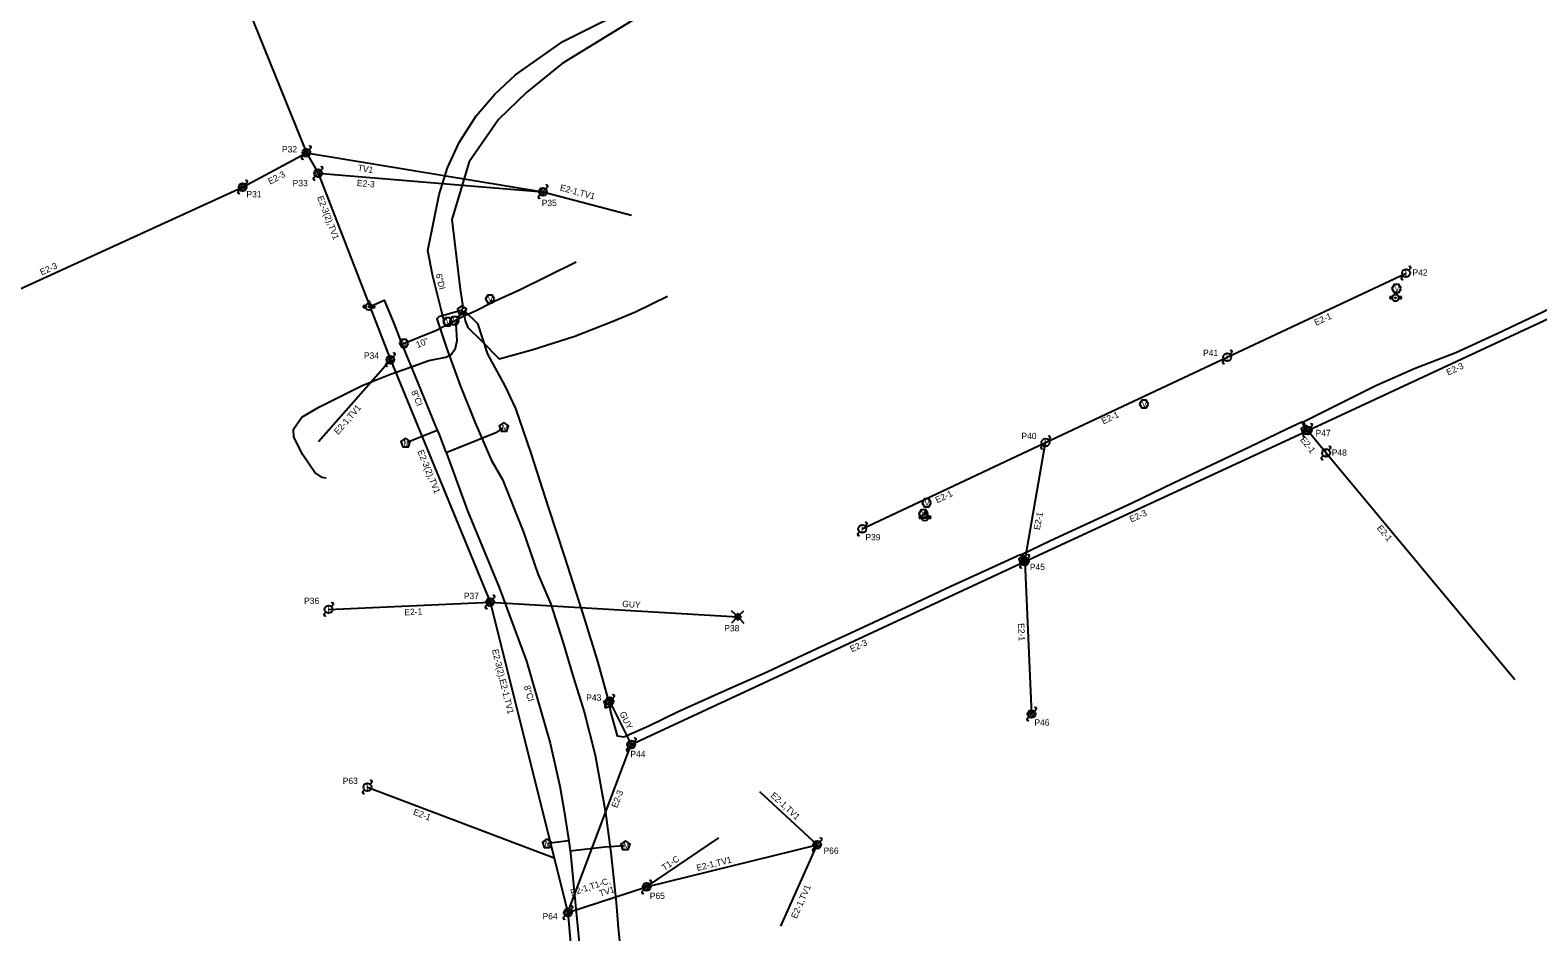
# Model space of a CAD drawing. Extents: x 1741604 to 1825760, y 1164229 to 1194908.
# Drawn here: x 1755902 to 1756853, y 1168887 to 1169455 of the extents above; entities that cross this region are included whole.
import ezdxf

# ---------------------------------------------------------------- set-up
doc = ezdxf.new("R2010")
doc.units = 0
for name, color, linetype in [('RD_EX_SU_H2O', 7, 'Continuous'), ('RD_EX_SU_Ovhd', 7, 'Continuous'), ('RD_EX_SU_Pole', 7, 'Continuous'), ('RD_EX_SU_Telecom', 7, 'Continuous'), ('RD_EX_SU_TX_H2O', 7, 'Continuous'), ('RD_EX_SU_TX_Pole', 7, 'Continuous')]:
    doc.layers.add(name, color=color, linetype=linetype)

# ---------------------------------------------------------------- blocks, each defined once
blk = doc.blocks.new('SUE_PP')
at = {"layer": 'RD_EX_SU_Pole'}
for p, q in [((-2.41, -0.65), (0.65, 2.41)), ((-1.77, -1.77), (1.77, 1.77)), ((-0.65, -2.41), (2.41, 0.65)), ((1.77, 1.77), (2.83, 2.83)), ((-2.83, -2.83), (-1.77, -1.77))]:
    blk.add_line(p, q, dxfattribs=at)
blk.add_circle((0, 0), 2.5, dxfattribs=at)
for centre, start, end in [((2.3, 3.36), 315, 135), ((-2.3, -3.36), 135, 315)]:
    blk.add_arc(centre, 0.75, start, end, dxfattribs=at)
blk = doc.blocks.new('SUE_TPP')
at = {"layer": 'RD_EX_SU_Telecom'}
blk.add_lwpolyline([(0, 3), (-2.85, 0.93), (-1.76, -2.43), (1.76, -2.43), (2.85, 0.93)], close=True, dxfattribs=at)
blk.add_text('T', height=3.75, dxfattribs=at).set_placement((-1.25, -1.88))
blk = doc.blocks.new('SUE_WV')
at = {"layer": 'RD_EX_SU_H2O'}
blk.add_lwpolyline([(2.89, 0), (1.44, 2.5), (-1.44, 2.5), (-2.89, 0), (-1.44, -2.5), (1.44, -2.5)], close=True, dxfattribs=at)
blk.add_text('V', height=3.75, dxfattribs=at).set_placement((-1.43, -1.88))
blk = doc.blocks.new('SUE_WFH')
at = {"layer": 'RD_EX_SU_H2O'}
for p, q in [((-2.01, 0.6), (-3.65, 0.6)), ((-3.65, 0.6), (-3.65, -0.45)), ((-0.48, 3.38), (-0.48, 2.04)), ((0.57, 3.38), (-0.48, 3.38)), ((0.57, 2.02), (0.57, 3.38)), ((3.7, 0.6), (2.01, 0.6)), ((3.7, -0.45), (3.7, 0.6)), ((-3.65, -0.45), (-2.05, -0.45)), ((2.05, -0.45), (3.7, -0.45))]:
    blk.add_line(p, q, dxfattribs=at)
for radius in [2.1, 0.263]:
    blk.add_circle((0, 0), radius, dxfattribs=at)
for start, end in [(163.3387, 192.31502), (74.24552, 103.21276), (347.68498, 16.6613)]:
    blk.add_arc((0, 0), 2.1, start, end, dxfattribs=at)

msp = doc.modelspace()

# ---------------------------------------------------------------- linework, layer by layer
at = {"layer": 'RD_EX_SU_H2O'}
for p, q in [((1756114.04, 1169281.57), (1756112.41, 1169281.57)), ((1756112.41, 1169281.57), (1756112.41, 1169280.52)), ((1756112.41, 1169280.52), (1756114, 1169280.52)), ((1756115.57, 1169284.35), (1756115.57, 1169283.01)), ((1756116.62, 1169284.35), (1756115.57, 1169284.35)), ((1756116.62, 1169282.99), (1756116.62, 1169284.35)), ((1756119.76, 1169281.57), (1756118.07, 1169281.57)), ((1756118.11, 1169280.52), (1756119.76, 1169280.52)), ((1756119.76, 1169280.52), (1756119.76, 1169281.57)), ((1756192.8, 1169285.36), (1756193.52, 1169283.69)), ((1756140.14, 1169195.61), (1756159.15, 1169203.19)), ((1756228.85, 1168942.71), (1756241.95, 1168944.59))]:
    msp.add_line(p, q, dxfattribs=at)
for points in [[(1756117.26, 1169281.48), (1756125.79, 1169285.31), (1756131.69, 1169271.16), (1756136.92, 1169257.42), (1756158.68, 1169266.39), (1756164.09, 1169269.14), (1756156.1, 1169301.1), (1756153.22, 1169316.48), (1756160.46, 1169351.88), (1756165.6, 1169368.56), (1756172.98, 1169384.55), (1756183.81, 1169401.45), (1756195.48, 1169415.16), (1756208.57, 1169427.28), (1756238.45, 1169448.31), (1756289.53, 1169473.78)], [(1756164.09, 1169269.14), (1756176.65, 1169275.59), (1756184.08, 1169278.93), (1756192.67, 1169283.36), (1756195.38, 1169284.48), (1756210.97, 1169291.74), (1756246.8, 1169309.46)], [(1756136.92, 1169257.42), (1756145.19, 1169237.03), (1756158.51, 1169204.61), (1756160.4, 1169200.45), (1756164.21, 1169190.42), (1756165.21, 1169188.06), (1756178.36, 1169152.4), (1756198.2, 1169104.01), (1756215.37, 1169057.62)], [(1756164.74, 1169189.16), (1756185.13, 1169197.4), (1756197.27, 1169202.12), (1756200.75, 1169204.77)], [(1756215.37, 1169057.62), (1756230.39, 1169005.87), (1756236.54, 1168978.79), (1756239.26, 1168962.91), (1756241.89, 1168945.6), (1756243.12, 1168936.58), (1756246.24, 1168905.88), (1756248.65, 1168879.97), (1756248.92, 1168877.19), (1756251.65, 1168846.26), (1756255.24, 1168799.63), (1756260.07, 1168747.12), (1756263.99, 1168702.78), (1756264.18, 1168700.31), (1756266.66, 1168666.35), (1756270.56, 1168620.84), (1756271.23, 1168612.87), (1756274.2, 1168580.03), (1756274.73, 1168575.57), (1756277.71, 1168539.82), (1756281.24, 1168499.51), (1756281.45, 1168495.4), (1756285.17, 1168453.36)], [(1756242.75, 1168938.05), (1756264.92, 1168940.41), (1756277.23, 1168941.33)]]:
    msp.add_lwpolyline(points, dxfattribs=at)
for points in [[(1756195.36, 1169285.95), (1756193.92, 1169288.45), (1756191.03, 1169288.45), (1756189.59, 1169285.95), (1756191.03, 1169283.45), (1756193.92, 1169283.45)], [(1756168.66, 1169271.63), (1756167.22, 1169274.13), (1756164.33, 1169274.13), (1756162.89, 1169271.63), (1756164.33, 1169269.13), (1756167.22, 1169269.13)], [(1756172.95, 1169272.27), (1756171.51, 1169274.77), (1756168.62, 1169274.77), (1756167.18, 1169272.27), (1756168.62, 1169269.77), (1756171.51, 1169269.77)], [(1756141.11, 1169258.01), (1756139.67, 1169260.51), (1756136.78, 1169260.51), (1756135.34, 1169258.01), (1756136.78, 1169255.51), (1756139.67, 1169255.51)], [(1756201.19, 1169208.05), (1756198.29, 1169205.95), (1756199.4, 1169202.54), (1756202.99, 1169202.54), (1756204.09, 1169205.95)], [(1756139.23, 1169198.29), (1756136.33, 1169196.19), (1756137.43, 1169192.78), (1756141.02, 1169192.78), (1756142.13, 1169196.19)], [(1756228.37, 1168945.6), (1756225.47, 1168943.49), (1756226.58, 1168940.08), (1756230.16, 1168940.08), (1756231.27, 1168943.49)], [(1756277.85, 1168944.39), (1756274.95, 1168942.28), (1756276.05, 1168938.87), (1756279.64, 1168938.87), (1756280.75, 1168942.28)]]:
    msp.add_lwpolyline(points, close=True, dxfattribs=at)
for radius in [2.1, 0.263]:
    msp.add_circle((1756116.05, 1169280.97), radius, dxfattribs=at)
for start, end in [(163.3387, 192.31502), (74.24552, 103.21276), (347.68498, 16.6613)]:
    msp.add_arc((1756116.05, 1169280.97), 2.1, start, end, dxfattribs=at)
at = {"layer": 'RD_EX_SU_Ovhd'}
for p, q in [((1755964.26, 1169656.78), (1756076.65, 1169378.21)), ((1756076.65, 1169378.21), (1756225.79, 1169353.6)), ((1756084.02, 1169365.23), (1756225.79, 1169353.6)), ((1756084.02, 1169365.23), (1756129.61, 1169247.62)), ((1755764.94, 1169232.37), (1756036.49, 1169356.49)), ((1756225.79, 1169353.6), (1756281.7, 1169338.72)), ((1756708.15, 1169203.09), (1757001.63, 1169339.59)), ((1756657.35, 1169249.33), (1756770.13, 1169302.28)), ((1756084.4, 1169196.1), (1756129.61, 1169247.62)), ((1756129.61, 1169247.62), (1756192.55, 1169094.86)), ((1756542.74, 1169195.47), (1756657.35, 1169249.33)), ((1756529.65, 1169120.5), (1756708.15, 1169203.09)), ((1756427.17, 1169140.99), (1756542.74, 1169195.47)), ((1756529.65, 1169120.5), (1756542.74, 1169195.47)), ((1756281.55, 1169005.03), (1756529.65, 1169120.5)), ((1756529.65, 1169120.5), (1756533.93, 1169024.26)), ((1756192.55, 1169094.86), (1756241.59, 1168899.03)), ((1756267.9, 1169032.3), (1756281.55, 1169005.03)), ((1756241.59, 1168899.03), (1756281.55, 1169005.03)), ((1756115.15, 1168978.19), (1756232.96, 1168933.48)), ((1756362.31, 1168975.41), (1756398.76, 1168941.84)), ((1756291.24, 1168915.26), (1756336.85, 1168946.15)), ((1756291.24, 1168915.26), (1756398.76, 1168941.84)), ((1756375.79, 1168890.43), (1756398.76, 1168941.84)), ((1756241.59, 1168899.03), (1756291.24, 1168915.26)), ((1756241.59, 1168899.03), (1756253.88, 1168753.63))]:
    msp.add_line(p, q, dxfattribs=at)
for points in [[(1756036.49, 1169356.49), (1756076.65, 1169378.21)], [(1756076.65, 1169378.21), (1756084.02, 1169365.23)], [(1756708.15, 1169203.09), (1756719.69, 1169188.85), (1756838.63, 1169046.08)], [(1756090.65, 1169090.26), (1756192.55, 1169094.86)], [(1756192.55, 1169094.86), (1756348.64, 1169085.45)]]:
    msp.add_lwpolyline(points, dxfattribs=at)
at = {"layer": 'RD_EX_SU_Pole'}
for p, q in [((1756073.82, 1169375.38), (1756074.88, 1169376.44)), ((1756074.23, 1169377.56), (1756077.29, 1169380.62)), ((1756074.88, 1169376.44), (1756078.42, 1169379.97)), ((1756076, 1169375.79), (1756079.06, 1169378.85)), ((1756078.42, 1169379.97), (1756079.48, 1169381.04)), ((1756081.6, 1169364.58), (1756084.66, 1169367.64)), ((1756082.25, 1169363.46), (1756085.79, 1169366.99)), ((1756083.37, 1169362.81), (1756086.43, 1169365.87)), ((1756085.79, 1169366.99), (1756086.85, 1169368.05)), ((1756033.66, 1169353.66), (1756034.72, 1169354.73)), ((1756034.07, 1169355.85), (1756037.14, 1169358.91)), ((1756034.72, 1169354.73), (1756038.26, 1169358.26)), ((1756035.84, 1169354.08), (1756038.9, 1169357.14)), ((1756038.26, 1169358.26), (1756039.32, 1169359.32)), ((1756081.19, 1169362.4), (1756082.25, 1169363.46)), ((1756223.38, 1169352.95), (1756226.44, 1169356.01)), ((1756224.03, 1169351.83), (1756227.56, 1169355.37)), ((1756227.56, 1169355.37), (1756228.62, 1169356.43)), ((1756222.97, 1169350.77), (1756224.03, 1169351.83)), ((1756225.15, 1169351.18), (1756228.21, 1169354.25)), ((1756767.3, 1169299.45), (1756768.36, 1169300.51)), ((1756771.9, 1169304.05), (1756772.96, 1169305.11)), ((1756659.12, 1169251.1), (1756660.18, 1169252.16)), ((1756654.52, 1169246.5), (1756655.58, 1169247.57)), ((1756705.74, 1169202.44), (1756708.8, 1169205.5)), ((1756706.38, 1169201.32), (1756709.92, 1169204.85)), ((1756707.5, 1169200.67), (1756710.57, 1169203.73)), ((1756709.92, 1169204.85), (1756710.98, 1169205.91)), ((1756539.91, 1169192.64), (1756540.97, 1169193.7)), ((1756544.5, 1169197.23), (1756545.57, 1169198.29)), ((1756705.32, 1169200.26), (1756706.38, 1169201.32)), ((1756716.86, 1169186.02), (1756717.92, 1169187.08)), ((1756721.46, 1169190.61), (1756722.52, 1169191.67)), ((1756424.34, 1169138.16), (1756425.4, 1169139.22)), ((1756428.94, 1169142.76), (1756430, 1169143.82)), ((1756526.82, 1169117.67), (1756527.88, 1169118.73)), ((1756527.23, 1169119.85), (1756530.29, 1169122.91)), ((1756527.88, 1169118.73), (1756531.41, 1169122.26)), ((1756529, 1169118.08), (1756532.06, 1169121.14)), ((1756531.41, 1169122.26), (1756532.48, 1169123.33)), ((1756194.32, 1169096.63), (1756195.38, 1169097.69)), ((1756087.82, 1169087.43), (1756088.89, 1169088.49)), ((1756092.42, 1169092.03), (1756093.48, 1169093.09)), ((1756189.72, 1169092.03), (1756190.78, 1169093.09)), ((1756190.13, 1169094.21), (1756193.2, 1169097.27)), ((1756190.78, 1169093.09), (1756194.32, 1169096.63)), ((1756191.9, 1169092.44), (1756194.96, 1169095.5)), ((1756347.58, 1169086.51), (1756344.75, 1169089.34)), ((1756349.67, 1169086.57), (1756352.51, 1169089.41)), ((1756347.53, 1169084.4), (1756344.7, 1169081.58)), ((1756349.7, 1169084.39), (1756352.53, 1169081.56)), ((1756265.49, 1169031.65), (1756268.55, 1169034.71)), ((1756266.14, 1169030.53), (1756269.67, 1169034.07)), ((1756267.26, 1169029.88), (1756270.32, 1169032.95)), ((1756269.67, 1169034.07), (1756270.73, 1169035.13)), ((1756265.08, 1169029.47), (1756266.14, 1169030.53)), ((1756278.73, 1169002.2), (1756279.79, 1169003.26)), ((1756279.14, 1169004.38), (1756282.2, 1169007.44)), ((1756279.79, 1169003.26), (1756283.32, 1169006.79)), ((1756280.91, 1169002.61), (1756283.97, 1169005.67)), ((1756283.32, 1169006.79), (1756284.38, 1169007.85)), ((1756112.32, 1168975.37), (1756113.38, 1168976.43)), ((1756116.92, 1168979.96), (1756117.98, 1168981.02)), ((1756395.93, 1168939.01), (1756396.99, 1168940.08)), ((1756396.34, 1168941.2), (1756399.41, 1168944.26)), ((1756396.99, 1168940.08), (1756400.53, 1168943.61)), ((1756398.11, 1168939.43), (1756401.17, 1168942.49)), ((1756400.53, 1168943.61), (1756401.59, 1168944.67)), ((1756288.83, 1168914.61), (1756291.89, 1168917.67)), ((1756289.47, 1168913.49), (1756293.01, 1168917.02)), ((1756293.01, 1168917.02), (1756294.07, 1168918.08)), ((1756288.41, 1168912.43), (1756289.47, 1168913.49)), ((1756290.59, 1168912.84), (1756293.65, 1168915.9))]:
    msp.add_line(p, q, dxfattribs=at)
for points in [[(1756348.64, 1169083.33), (1756350.76, 1169085.45), (1756348.64, 1169087.57), (1756346.52, 1169085.45)], [(1756348.64, 1169084.74), (1756349.35, 1169085.45), (1756348.64, 1169086.16), (1756347.94, 1169085.45)]]:
    msp.add_lwpolyline(points, close=True, dxfattribs=at)
for centre in [(1756076.65, 1169378.21), (1756084.02, 1169365.23), (1756036.49, 1169356.49), (1756225.79, 1169353.6), (1756770.13, 1169302.28), (1756657.35, 1169249.33), (1756708.15, 1169203.09), (1756542.74, 1169195.47), (1756719.69, 1169188.85), (1756427.17, 1169140.99), (1756529.65, 1169120.5), (1756090.65, 1169090.26), (1756192.55, 1169094.86), (1756267.9, 1169032.3), (1756281.55, 1169005.03), (1756115.15, 1168978.19), (1756398.76, 1168941.84), (1756291.24, 1168915.26)]:
    msp.add_circle(centre, 2.5, dxfattribs=at)
for centre, start, end in [((1756074.35, 1169374.85), 135, 315), ((1756078.95, 1169381.57), 315, 135), ((1756086.32, 1169368.58), 315, 135), ((1756038.79, 1169359.85), 315, 135), ((1756081.72, 1169361.87), 135, 315), ((1756228.09, 1169356.96), 315, 135), ((1756034.19, 1169353.13), 135, 315), ((1756223.5, 1169350.24), 135, 315), ((1756767.83, 1169298.92), 135, 315), ((1756772.43, 1169305.64), 315, 135), ((1756659.65, 1169252.69), 315, 135), ((1756655.05, 1169245.97), 135, 315), ((1756710.45, 1169206.44), 315, 135), ((1756545.04, 1169198.82), 315, 135), ((1756705.85, 1169199.73), 135, 315), ((1756721.99, 1169192.2), 315, 135), ((1756540.44, 1169192.11), 135, 315), ((1756717.39, 1169185.49), 135, 315), ((1756424.87, 1169137.63), 135, 315), ((1756429.47, 1169144.35), 315, 135), ((1756527.35, 1169117.14), 135, 315), ((1756531.95, 1169123.86), 315, 135), ((1756194.85, 1169098.22), 315, 135), ((1756092.95, 1169093.62), 315, 135), ((1756190.25, 1169091.5), 135, 315), ((1756088.36, 1169086.9), 135, 315), ((1756270.2, 1169035.66), 315, 135), ((1756265.61, 1169028.94), 135, 315), ((1756283.85, 1169008.38), 315, 135), ((1756279.26, 1169001.67), 135, 315), ((1756112.85, 1168974.84), 135, 315), ((1756117.45, 1168981.55), 315, 135), ((1756401.06, 1168945.2), 315, 135), ((1756396.46, 1168938.48), 135, 315), ((1756293.54, 1168918.61), 315, 135), ((1756288.94, 1168911.9), 135, 315)]:
    msp.add_arc(centre, 0.75, start, end, dxfattribs=at)
at = {"layer": 'RD_EX_SU_Telecom'}
for points in [[(1756549.94, 1169589.96), (1756541.82, 1169587), (1756513.59, 1169574.05), (1756488.12, 1169561.24), (1756457.84, 1169546.06), (1756427.48, 1169532.35), (1756381.3, 1169509.82), (1756347.29, 1169493.22), (1756314.45, 1169477.96), (1756280.78, 1169460.79), (1756237.9, 1169434.39), (1756215.68, 1169416.31), (1756197.86, 1169399.08), (1756179.37, 1169372.51), (1756168.44, 1169336.07), (1756173.6, 1169292.17), (1756175.56, 1169279.77)], [(1756706.93, 1169203.78), (1756705.63, 1169208.7), (1756739.31, 1169225.47), (1756751.07, 1169231.4), (1756775.8, 1169242.36), (1756801.58, 1169252.27), (1756827.44, 1169264.14), (1756856.35, 1169277.94), (1756883.6, 1169291.76), (1756909.38, 1169304.26), (1756928.56, 1169314.26), (1756954.07, 1169326.93), (1756971.08, 1169334.18), (1756992.88, 1169344.76), (1756994.71, 1169344.5), (1756998.78, 1169338.96)], [(1756089.12, 1169173.04), (1756086.65, 1169173.38), (1756081.94, 1169176.62), (1756074.48, 1169187.62), (1756068.67, 1169198.86), (1756068.63, 1169203.96), (1756073.77, 1169211.42), (1756084.56, 1169217.8), (1756111.95, 1169231.42), (1756129.67, 1169238.55), (1756141.79, 1169242.8), (1756153.95, 1169247.16), (1756164.59, 1169249.34), (1756168, 1169250.87), (1756170.7, 1169254.95), (1756171.72, 1169259.74), (1756171.16, 1169269.95), (1756172.35, 1169274.16), (1756175.02, 1169278.56)], [(1756174.94, 1169278.95), (1756160.29, 1169274.63), (1756159.03, 1169273.37), (1756165.27, 1169254.63), (1756173.7, 1169231.35), (1756183.01, 1169207.77), (1756193.5, 1169184.2), (1756200.36, 1169172.13), (1756213.48, 1169138.98), (1756222.54, 1169112.66), (1756230.85, 1169093.5), (1756238.34, 1169069.67), (1756245.15, 1169047.16), (1756251.74, 1169025.59), (1756258.67, 1168998.39), (1756265.3, 1168962.17), (1756268.66, 1168936.68), (1756271.99, 1168905.49), (1756273.23, 1168889.45), (1756275.78, 1168864.66), (1756278.96, 1168829.09), (1756282.05, 1168791.5), (1756284.91, 1168753.06), (1756286.16, 1168737.41)], [(1756175.64, 1169278.57), (1756176.8, 1169272.09), (1756178.49, 1169267.95), (1756187.47, 1169259.23), (1756198.15, 1169248.32), (1756218.82, 1169253.84), (1756245.92, 1169262.46), (1756269.52, 1169271.71), (1756284.29, 1169277.95), (1756304.3, 1169287.7)], [(1756176.03, 1169278.89), (1756184.48, 1169270.45), (1756187.46, 1169261.37), (1756190.92, 1169251.19), (1756201.82, 1169231.14), (1756208.51, 1169216.95), (1756218.28, 1169188.69), (1756229.17, 1169154.65), (1756239.35, 1169123.41), (1756251.8, 1169084.59), (1756260.51, 1169056.77), (1756267.26, 1169032.33)], [(1756528.65, 1169121.51), (1756527.55, 1169124.87), (1756545.53, 1169133.42), (1756570.43, 1169144.95), (1756597.28, 1169157.47), (1756623.52, 1169170.13), (1756671.31, 1169192.7), (1756694.88, 1169204.15), (1756704.43, 1169208.56), (1756706.72, 1169203.7)], [(1756407.62, 1169069.71), (1756419.97, 1169075.52), (1756457.59, 1169092.82), (1756483.12, 1169104.94), (1756504.27, 1169114.56), (1756526.75, 1169124.76), (1756528.39, 1169121.46)], [(1756267.32, 1169030.87), (1756268.59, 1169024.7), (1756272.67, 1169010.46), (1756276.84, 1169009.94), (1756292.62, 1169016.76), (1756311.15, 1169025.82), (1756338.22, 1169037.98), (1756367.14, 1169050.95), (1756386.4, 1169059.87), (1756407.62, 1169069.71)]]:
    msp.add_lwpolyline(points, dxfattribs=at)
for points in [[(1756174.83, 1169281.88), (1756171.97, 1169279.81), (1756173.06, 1169276.45), (1756176.59, 1169276.45), (1756177.68, 1169279.81)], [(1756267.06, 1169034.26), (1756264.21, 1169032.19), (1756265.3, 1169028.84), (1756268.82, 1169028.84), (1756269.91, 1169032.19)]]:
    msp.add_lwpolyline(points, close=True, dxfattribs=at)

# ---------------------------------------------------------------- block references
at = {"layer": 'RD_EX_SU_H2O'}
for name, p in [('SUE_WFH', (1756763.48, 1169286.61)), ('SUE_WV', (1756764.1, 1169292.55)), ('SUE_WV', (1756604.85, 1169219.72)), ('SUE_WV', (1756467.82, 1169157.49)), ('SUE_WV', (1756465.78, 1169150.41)), ('SUE_WFH', (1756466.64, 1169148.2))]:
    msp.add_blockref(name, p, dxfattribs=at)
at = {"layer": 'RD_EX_SU_Pole'}
for p in [(1756129.61, 1169247.62), (1756533.93, 1169024.26), (1756241.59, 1168899.03)]:
    msp.add_blockref('SUE_PP', p, dxfattribs=at)
at = {"layer": 'RD_EX_SU_Telecom'}
for p in [(1756706.83, 1169203.41), (1756528.77, 1169121.17)]:
    msp.add_blockref('SUE_TPP', p, dxfattribs=at)

# ---------------------------------------------------------------- texts
at = {"layer": 'RD_EX_SU_H2O'}
for s, p in [('V', (1756191.04, 1169284.07)), ('V', (1756164.57, 1169269.75)), ('V', (1756168.85, 1169270.39)), ('V', (1756137.02, 1169256.14)), ('M', (1756199.82, 1169203.01)), ('M', (1756137.86, 1169193.25)), ('M', (1756226.94, 1168940.67)), ('M', (1756276.41, 1168939.46))]:
    msp.add_text(s, height=3.75, dxfattribs=at).set_placement(p)
at = {"layer": 'RD_EX_SU_Ovhd'}
for s, rotation, p in [('E2-3', 28.3997, (1756053.82, 1169357.98)), ('TV1', 350.63088, (1756108.81, 1169366.82)), ('E2-3', 355.31166, (1756108.37, 1169357.21)), ('E2-1,TV1', 345.10097, (1756236.26, 1169354.46)), ('E2-3(2),TV1', 291.01616, (1756083.39, 1169350.12)), ('E2-3', 24.5651, (1755909.79, 1169300.78)), ('E2-1', 25.14887, (1756713.36, 1169269)), ('E2-3', 24.94368, (1756796.62, 1169237.62)), ('E2-1,TV1', 49.09935, (1756096.68, 1169200.1)), ('E2-1', 25.17337, (1756579.22, 1169206.84)), ('E2-1', 309.01406, (1756703.06, 1169197.07)), ('E2-3(2),TV1', 292.34622, (1756146.62, 1169189.81)), ('E2-1', 25.2386, (1756474.39, 1169157.09)), ('E2-1', 80.09561, (1756539.16, 1169140.09)), ('E2-3', 24.82835, (1756596.82, 1169144.96)), ('E2-1', 309.79882, (1756751.43, 1169141.37)), ('E2-1', 2.58441, (1756138.52, 1169086.41)), ('GUY', 356.55058, (1756275.74, 1169091.79)), ('E2-1', 272.54526, (1756525.38, 1169081.46)), ('E2-3', 24.95904, (1756420.6, 1169063.13)), ('E2-3(2),E2-1,TV1', 283.92649, (1756193.68, 1169064.6)), ('GUY', 296.58846, (1756273.97, 1169024.64)), ('E2-3', 69.10694, (1756272.58, 1168964.69)), ('E2-1,TV1', 317.35954, (1756369.05, 1168972.41)), ('E2-1', 339.21842, (1756143.68, 1168960.95)), ('T1-C', 34.1187, (1756302.44, 1168925.26)), ('E2-1,TV1', 13.88964, (1756323.21, 1168925.22)), ('E2-1,T1-C,', 17.90832, (1756243.92, 1168909.46)), ('TV1', 17.90832, (1756262.06, 1168909.02)), ('E2-1,TV1', 65.92817, (1756385.73, 1168894.86))]:
    msp.add_text(s, height=4, rotation=rotation, dxfattribs=at).set_placement(p)
at = {"layer": 'RD_EX_SU_Pole'}
for p in [(1756769.27, 1169300.28), (1756656.49, 1169247.33), (1756541.87, 1169193.47), (1756718.83, 1169186.85), (1756426.31, 1169138.99), (1756089.79, 1169088.26), (1756114.29, 1168976.19)]:
    msp.add_text('L', height=4, dxfattribs=at).set_placement(p)
at = {"layer": 'RD_EX_SU_Telecom'}
for p in [(1756173.6, 1169276.65), (1756265.83, 1169029.04)]:
    msp.add_text('T', height=3.75, dxfattribs=at).set_placement(p)
at = {"layer": 'RD_EX_SU_TX_H2O'}
for s, rotation, p in [('6"DI', 284.04063, (1756158.08, 1169301.43)), ('10"', 22.40205, (1756146.78, 1169255)), ('8"CI', 292.33795, (1756142.65, 1169227.43)), ('8"CI', 286.17798, (1756213.77, 1169041.61))]:
    msp.add_text(s, height=4, rotation=rotation, dxfattribs=at).set_placement(p)
at = {"layer": 'RD_EX_SU_TX_Pole'}
for s, p in [('P32', (1756061.28, 1169378.35)), ('P33', (1756068.03, 1169357.05)), ('P31', (1756038.89, 1169350.06)), ('P35', (1756225.08, 1169344.51)), ('P42', (1756774.11, 1169300.63)), ('P34', (1756112.96, 1169248.3)), ('P41', (1756642.1, 1169249.95)), ('P47', (1756713.05, 1169199.45)), ('P40', (1756527.56, 1169197.58)), ('P48', (1756723.21, 1169187.09)), ('P39', (1756429.17, 1169133.73)), ('P45', (1756532.85, 1169115)), ('P36', (1756075.21, 1169093.63)), ('P37', (1756175.95, 1169096.7)), ('P38', (1756340.18, 1169076.35)), ('P43', (1756253.13, 1169032.6)), ('P46', (1756535.78, 1169016.89)), ('P44', (1756280.98, 1168997.04)), ('P63', (1756099.58, 1168980.11)), ('P66', (1756402.76, 1168936.06)), ('P65', (1756293.21, 1168907.6)), ('P64', (1756225.59, 1168894.75))]:
    msp.add_text(s, height=4, dxfattribs=at).set_placement(p)

doc.saveas('drawing.dxf')
